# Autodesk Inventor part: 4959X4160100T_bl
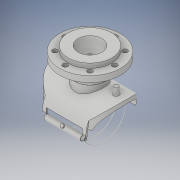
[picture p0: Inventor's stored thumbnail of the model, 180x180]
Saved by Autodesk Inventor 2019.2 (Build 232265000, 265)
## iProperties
Created: 2020-06
Part Number: 4959X4160100T_bl
Material: Generic
Description: Plasson Flanged Branch Saddle 160x100
Document SubType Name: Modeling
Designer: KIM
Density: 1 g/cm^3
Appearance: Default
Author: KIM
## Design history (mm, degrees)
derived "4959X4.ipt"
feature "Solid1::4959X4.ipt" dims "ScaleForDerivedMember" = 10
feature "Solid2::4959X4.ipt" dims "ScaleForDerivedMember" = 10
tag "TaggingFeature1"
body "Solid1"
body "Solid2"
other parameters: "d0" = 263 [user parameter], "d4" = 119 [user parameter], "d7" = 87 [user parameter], "d10" = 0.5 [user parameter], "d11" = 1 [user parameter], "d12" = 29.75 [user parameter], "d13" = 16 [user parameter], "d14" = 8 [user parameter], "d16" = 10 deg [user parameter], "d17" = 10 deg [user parameter], "d19" = 0 [user parameter], "d23" = 0 [user parameter], "d26" = 0 [user parameter], "d27" = 157.8 [user parameter], "d28" = 0 [user parameter], "d29" = 131.5 [user parameter], "d30" = 0 [user parameter], "d31" = 1 [user parameter], "d32" = 1 [user parameter], "d33" = 19.2 [user parameter], "d34" = 9.6 [user parameter], "d35" = 45 deg [user parameter], "d36" = 131.5 [user parameter], "d37" = 0 [user parameter], "d38" = 5 [user parameter], "d39" = 85 deg [user parameter], "d40" = 29.75 [user parameter], "d41" = 16 [user parameter], "d42" = 95.63636 [user parameter], "d49" = 3 [user parameter], "d50" = 6 [user parameter], "d51" = 5 [user parameter], "d54" = 0 [user parameter], "d57" = 35 deg [user parameter], "d60" = 16.4375 [user parameter], "d61" = 1 [user parameter], "d62" = 90 deg [user parameter], "d63" = 2 [user parameter], "d64" = 0 [user parameter], "d65" = 0 [user parameter], "d68" = 32.875 [user parameter], "d70" = 0.57711 [user parameter], "d71" = 10 deg [user parameter], "d73" = 4.9 [user parameter], "d75" = 22 [user parameter], "d77" = 89.25 [user parameter], "d78" = 105 [user parameter], "d79" = 158 [user parameter], "d80" = 1 [user parameter], "d81" = 104.4 [user parameter], "d82" = 121.8 [user parameter], "d83" = 1 [user parameter], "d84" = 16.5 [user parameter], "d87" = 18 [user parameter], "d95" = 360 deg [user parameter], "d_h" = 158 [user parameter], "B" = 219 [user parameter], "L" = 263 [user parameter], "LS" = 105 [user parameter], "H1" = 119 [user parameter], "Dt" = 16 [user parameter], "di" = 87 [user parameter], "s_" = 18 [user parameter], "t" = 22 [user parameter], "d72" = 14 [user parameter]
